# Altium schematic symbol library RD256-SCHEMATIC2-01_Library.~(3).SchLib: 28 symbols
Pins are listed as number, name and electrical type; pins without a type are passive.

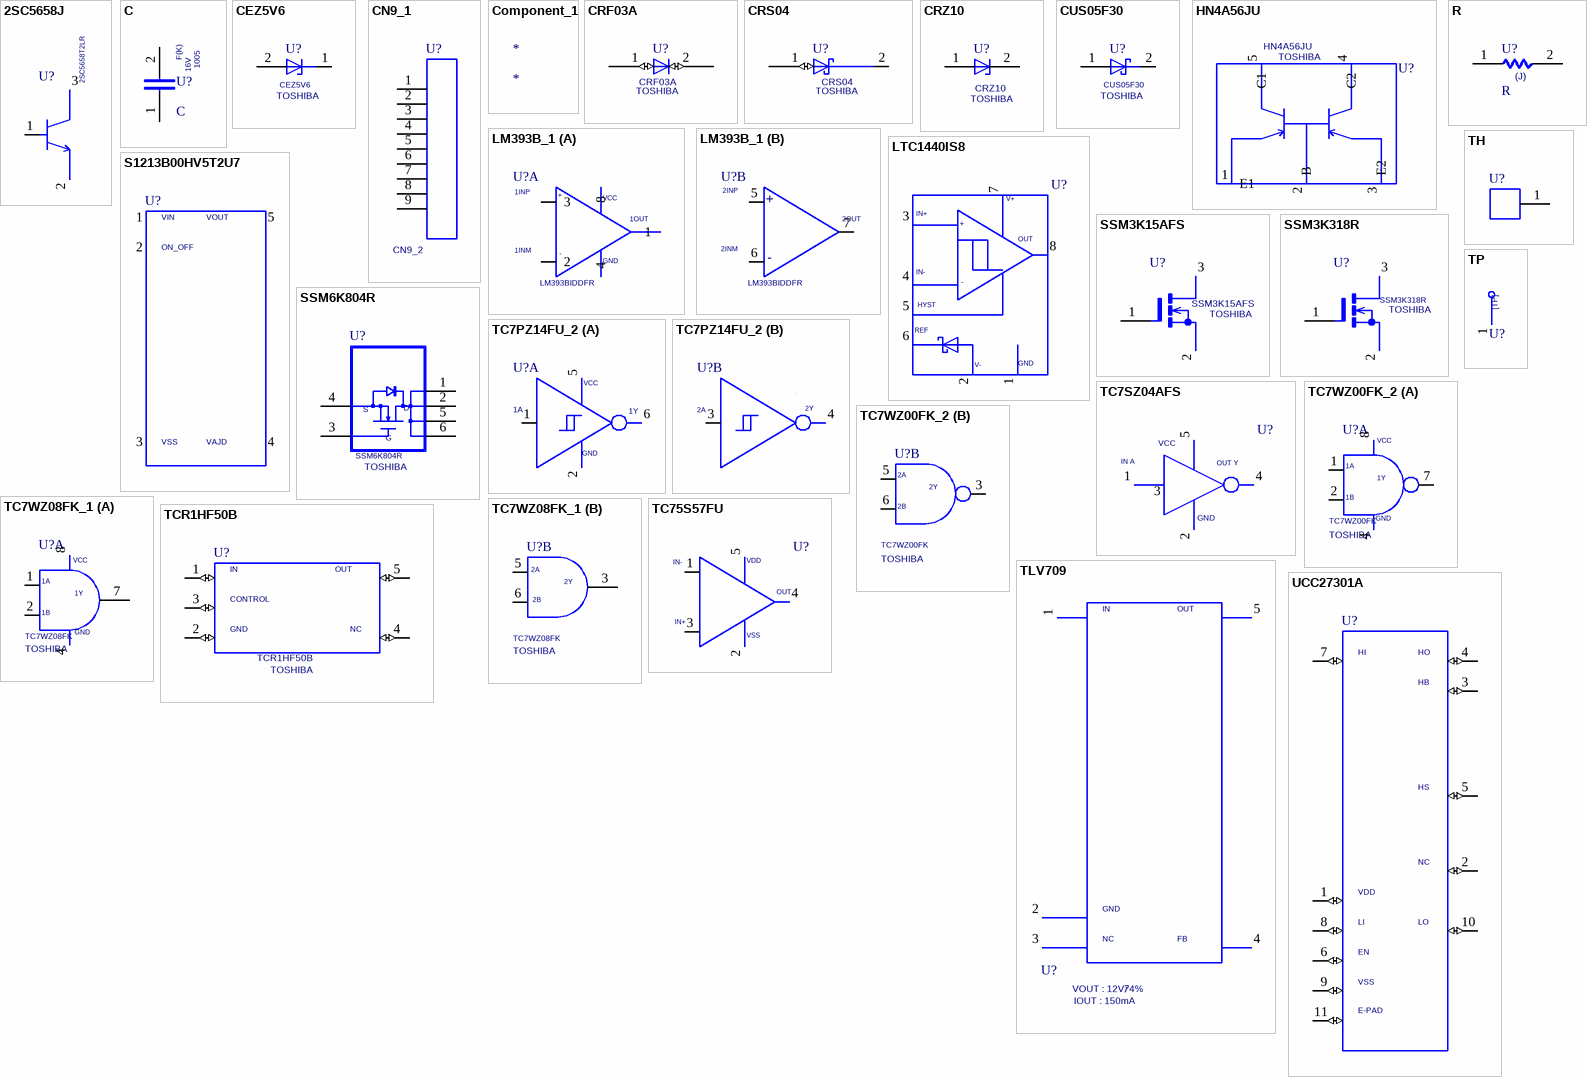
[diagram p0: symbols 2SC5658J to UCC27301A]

## 2SC5658J
designator U?  VAL1: 2SC5658T2LR  (hidden comment: 2SC5658J)
ORIGINALSYMBOLORIGIN: (0,0); PSPICETEMPLATE: X^@REFDES %C %B %E @MODEL; SAVEAREA0: -6194,-158,18648,15662; VENDOR: ROHM; SAVECOUNT: 8; UPDATETIME: 15:12:10; UPDATEUSER: 19910145; TIME: 09:39:04; Altium-Right: 20; Altium-Bottom: 80
simulation model 2SC5658J
pins: 1 B, 2 E, 3 C

## C
designator U?  VOLTAGE: 16VODE: 1005  VAL1: F(K)  (hidden comment: C)
ORIGINALSYMBOLORIGIN: (0,0); VC2: 0; PSPICETEMPLATE: C^@REFDES %1 %2 ?TOLERANCE¦C^@REFDES¦ @VALUE ?IC/IC=@IC/ TC=@TC1,@TC2 ?TOLERANCE¦\n.model C^@REFDES CAP C=1 DEV=@TOLERANCE% TC1=@TC1 TC2=@TC2 VC1=@VC1 VC2=@VC2¦; SAVECOUNT: 2; UPDATETIME: 08:48:12; UPDATEUSER: HP_Z8_KEYSHOT; Altium-Right: 20; Altium-Bottom: 10
simulation model C
pins: 1, 2

## CEZ5V6
designator U?  VENDOR: TOSHIBA  (hidden comment: CEZ5V6)
ORIGINALSYMBOLORIGIN: (0,0); PSPICETEMPLATE: X^@REFDES %C %A @MODEL; SAVEAREA0: -4630,-153,17114,13055; SAVECOUNT: 9; UPDATETIME: 08:16:22; UPDATEUSER: fukuda-y; TIME: 14:49:55; Altium-Right: 20
simulation model CEZ5V6
pins: 1 C, 2 A

## CN9_1
designator U?, comment CN9_2
OriginalSymbolOrigin: (0,0); USER_VALUE: XG4A-1031; COMP: CN9_1; PSPICETEMPLATE: X^@REFDES %1 %2 %3 %4 %5 %6 %7 %8 %9 %10 %M1 %M2 @MODEL; SAVECOUNT: 2; UPDATETIME: 08:48:13; UPDATEUSER: HP_Z8_KEYSHOT; Altium-Right: 20; Altium-Bottom: 120
simulation model CN9_1
pins: 1, 2, 3, 4, 5, 6, 7, 8, 9

## Component_1
designator *

## CRF03A
designator U?  VENDOR: TOSHIBA  (hidden comment: CRF03A)
OriginalSymbolOrigin: (0,0); PSPICETEMPLATE: X^@REFDES %A %C @MODEL; SAVECOUNT: 2; UPDATETIME: 08:48:14; UPDATEUSER: HP_Z8_KEYSHOT; Altium-Right: 10; Altium-Bottom: 20
simulation model CRF03A
pins: 1 A (io), 2 C (io)

## CRS04
designator U?  VENDOR: TOSHIBA  (hidden comment: CRS04)
OriginalSymbolOrigin: (0,0); PSPICETEMPLATE: X^@REFDES %A %C @MODEL; SAVECOUNT: 2; UPDATETIME: 08:48:14; UPDATEUSER: HP_Z8_KEYSHOT; Altium-Right: 40; Altium-Bottom: 20
simulation model CRS04
pins: 1 A (io), 2 C (io)

## CRZ10
designator U?  VENDOR: TOSHIBA  (hidden comment: CRZ10)
ORIGINALSYMBOLORIGIN: (0,0); PSPICETEMPLATE: X^@REFDES %A %C @MODEL; SAVEAREA0: -4630,-153,17114,13055; SAVECOUNT: 6; UPDATETIME: 08:18:42; UPDATEUSER: fukuda-y; TIME: 14:49:55; Altium-Right: 10; Altium-Bottom: 20
simulation model CRZ10
pins: 1 A, 2 C

## CUS05F30
designator U?  VENDOR: TOSHIBA  (hidden comment: CUS05F30)
ORIGINALSYMBOLORIGIN: (0,0); PSPICETEMPLATE: X^@REFDES %A %C @MODEL; SAVEAREA0: -4630,-153,17114,13055; SAVECOUNT: 9; UPDATETIME: 08:16:22; UPDATEUSER: fukuda-y; TIME: 14:49:55; Altium-Right: 20
simulation model CUS05F30
pins: 1 A, 2 C

## HN4A56JU
designator U?  VENDOR: TOSHIBA  (hidden comment: HN4A56JU)
OriginalSymbolOrigin: (0,0); PSPICETEMPLATE: X^@REFDES %B1 %E %B2 %C2 %C1 @MODEL; SAVECOUNT: 2; UPDATETIME: 08:48:13; UPDATEUSER: HP_Z8_KEYSHOT; Altium-Right: 120; Altium-Bottom: 80
simulation model HN4A56JU
pins: 1 E1 (io), 2 B (io), 3 E2 (io), 4 C2 (io), 5 C1 (io)

## LM393B_1
designator U?  VAL1: LM393BIDDFR  (hidden comment: LM393B_1)
OriginalSymbolOrigin: (2540,0); SWAP_INFO: (S1+S2); VENDOR: TI; COMP: LM393B_2; PSPICETEMPLATE: X^@REFDES %INN %VSS %INP %OUT %VDD @MODEL; SPLIT_INST: TRUE; SAVECOUNT: 5; UPDATETIME: 19:15:42; UPDATEUSER: t5459927; TIME: 08:48:12; Altium-Right: 70; Altium-Bottom: 60; Altium-Right1: 50
simulation model LM393B_1
part A pins: 1 (io), 2 (io), 3 (io), 4 (io), 8 (io)
part B pins: 5 (io), 6 (io), 7 (io)

## LTC1440IS8
designator U?  (value not drawn)
OriginalSymbolOrigin: (0,0); PSPICETEMPLATE: X^@REFDES %GND %V- %IN+ %IN- %HYST %REF %V+ %OUT @MODEL; SAVECOUNT: 4; UPDATETIME: 17:22:21; UPDATEUSER: t5459927; TIME: 08:48:16; Altium-Right: 90; Altium-Bottom: 120
simulation model LTC1440IS8
pins: 1 GND (io), 2 V- (io), 3 IN+ (io), 4 IN- (io), 5 HYST (io), 6 REF (io), 7 V+ (io), 8 OUT (io)

## R
designator U?  VAL1: (J)  (hidden comment: R)
ORIGINALSYMBOLORIGIN: (0,0); PSPICETEMPLATE: R^@REFDES %1 %2 ?TOLERANCE¦R^@REFDES¦ @VALUE TC=@TC1,@TC2 ?TOLERANCE¦\n.model R^@REFDES RES R=1 DEV=@TOLERANCE% TC1=@TC1 TC2=@TC2¦; TC2: 0; VAL2: 0.125; SAVECOUNT: 2; UPDATETIME: 08:48:13; UPDATEUSER: HP_Z8_KEYSHOT; Altium-Right: 20
simulation model R
pins: 1, 2

## S1213B00HV5T2U7
designator U?  (value not drawn)
OriginalSymbolOrigin: (0,0); PSPICETEMPLATE: X^@REFDES %ADJUST %OUTPUT %INPUT @MODEL; SAVECOUNT: 7; UPDATETIME: 09:48:38; UPDATEUSER: t5459927; TIME: 08:48:13; Altium-Right: 80; Altium-Bottom: 170
simulation model S1213B00HV5T2U7
pins: 1 (in), 2 (in), 3 (in), 4 (io), 5 (out)

## SSM3K15AFS
designator U?  VENDOR: TOSHIBA  (hidden comment: SSM3K15AFS)
PSPICETEMPLATE: X^@REFDES %D %G %S @MODEL; ORIGINALSYMBOLORIGIN: (0,0); SAVECOUNT: 2; UPDATETIME: 08:48:15; UPDATEUSER: HP_Z8_KEYSHOT; Altium-Right: 30; Altium-Bottom: 70
simulation model SSM3K15AFS
pins: 1 G, 2 S, 3 D

## SSM3K318R
designator U?  VENDOR: TOSHIBA  (hidden comment: SSM3K318R)
PSPICETEMPLATE: X^@REFDES %D %G %S @MODEL; ORIGINALSYMBOLORIGIN: (0,0); SAVECOUNT: 2; UPDATETIME: 08:48:16; UPDATEUSER: HP_Z8_KEYSHOT; Altium-Right: 30; Altium-Bottom: 70
simulation model SSM3K318R
pins: 1 G, 2 S, 3 D

## SSM6K804R
designator U?  VENDOR: TOSHIBA  (hidden comment: SSM6K804R)
PSPICETEMPLATE: X^@REFDES %1 %2 %3 %4 %5 %6 @MODEL; ORIGINALSYMBOLORIGIN: (0,0); SAVEAREA0: -7120,-295,29516,23636; SAVECOUNT: 14; UPDATETIME: 08:48:15; UPDATEUSER: HP_Z8_KEYSHOT; Altium-Right: 50; Altium-Bottom: 70
simulation model SSM6K804R
pins: 1, 2, 3, 4, 5, 6

## TC7PZ14FU_2
designator U?, comment TC7PZ17FU  (value not drawn)
OriginalSymbolOrigin: (5080,15240); SWAP_INFO: (S1+S2); VENDOR: TOSHIBA; COMP: TC7PZ17FU_2; PSPICETEMPLATE: X^@REFDES %1A %GND %2A %2Y %VCC %1Y @MODEL; SPLIT_INST: TRUE; SAVECOUNT: 7; UPDATETIME: 19:09:34; UPDATEUSER: t5459927; TIME: 11:55:01; Altium-Right: 70; Altium-Bottom: 60
simulation model TC7PZ14FU_2
part A pins: 1 (io), 2 (io), 5 (io), 6 (io)
part B pins: 3 (io), 4 (io)

## TC7SZ04AFS
designator U?  (value not drawn)
OriginalSymbolOrigin: (0,-5080); PSPICETEMPLATE: X^@REFDES %INA %GND %NC %OUTY %VCC @MODEL; VENDOR: TOSHIBA; SAVECOUNT: 6; UPDATETIME: 19:30:29; UPDATEUSER: t5459927; TIME: 11:55:02; Altium-Right: 80; Altium-Bottom: 60
simulation model TC7SZ04AFS
pins: 1 (io), 2 (io), 3 (io), 4 (io), 5 (io)

## TC7WZ00FK_2
designator U?, comment TC7WZ00FK  VENDOR: TOSHIBA
PART NUMBER: TC7W00FK; ORIGINALSYMBOLORIGIN: (2540,-2540); DESCRIPTION-A: NAND 2ch Logic; PSPICETEMPLATE: X^@REFDES %1A %1B %2Y %GND %2A %2B %1Y %VCC @MODEL; ・: 7 V; SPLIT_INST: TRUE; ORDER: $pOrder; COMP: TC7WZ00FK_2; SWAP_INFO: (S1+S2); SAVECOUNT: 9; UPDATETIME: 16:09:46; UPDATEUSER: sptcae09; TIME: 08:52:39; Altium-Right: 50; Altium-Bottom: 60; Altium-Bottom1: 40
simulation model TC7WZ00FK_2
part A pins: 1, 2, 4, 7, 8
part B pins: 3 2Y, 5 2A, 6 2B

## TC7WZ08FK_1
designator U?, comment TC7WZ08FK  VENDOR: TOSHIBA
PART NUMBER: TC7W00FK; ORIGINALSYMBOLORIGIN: (2540,-2540); DESCRIPTION-A: NAND 2ch Logic; PSPICETEMPLATE: X^@REFDES %1A %1B %2Y %GND %2A %2B %1Y %VCC @MODEL; ・: 7 V; SPLIT_INST: TRUE; ORDER: $pOrder; COMP: TC7WZ08FK_2; SWAP_INFO: (S1+S2); SAVECOUNT: 9; UPDATETIME: 16:09:46; UPDATEUSER: sptcae09; TIME: 08:52:39; Altium-Right: 40; Altium-Bottom: 60
simulation model TC7WZ08FK_1
part A pins: 1, 2, 4, 7, 8
part B pins: 3, 5, 6

## TC75S57FU
designator U?  (value not drawn)
OriginalSymbolOrigin: (2540,0); PSPICETEMPLATE: X^@REFDES %INN %VSS %INP %OUT %VDD @MODEL; VENDOR: TOSHIBA; SAVECOUNT: 3; UPDATETIME: 11:03:38; UPDATEUSER: t5459927; TIME: 08:48:15; Altium-Right: 60
simulation model TC75S57FU
pins: 1 (io), 2 (io), 3 (io), 4 (io), 5 (io)

## TCR1HF50B
designator U?  VENDOR: TOSHIBA
OriginalSymbolOrigin: (-2540,0); PSPICETEMPLATE: X^@REFDES %IN %GND %CONTROL %NC %OUT @MODEL; SAVECOUNT: 4; UPDATETIME: 10:27:35; UPDATEUSER: t5459927; TIME: 11:54:59; Altium-Right: 110; Altium-Bottom: 60
simulation model TCR1HF50B
pins: 1 (io), 2 (io), 3 (io), 4 (io), 5 (io)

## TH
designator U?  (value not drawn)
ORIGINALSYMBOLORIGIN: (0,0); PSPICETEMPLATE: X^@REFDES %1 @MODEL; SAVECOUNT: 1; UPDATETIME: 18:11:32; UPDATEUSER: w20165dm; Altium-Right: 20
simulation model TH
pins: 1

## TLV709
designator U?  CLASS: IOUT : 150mA  NC: VOUT : 12Vｱ4%  (hidden comment: TLV709)
OriginalSymbolOrigin: (0,0); VAL1: TLV709A01DBVR; PSPICETEMPLATE: X^@REFDES %IN %GND %NC %FB %OUT @MODEL; SAVECOUNT: 5; UPDATETIME: 10:01:49; UPDATEUSER: t5459927; TIME: 08:48:16; Altium-Right: 140; Altium-Bottom: 240
simulation model TLV709
pins: 1 (io), 2 (io), 3 (io), 4 (io), 5 (io)

## TP
designator U?  (value not drawn)
ORIGINALSYMBOLORIGIN: (0,0); SAVEAREA0: -242,-92,12810,7836; SAVECOUNT: 2; UPDATETIME: 16:18:11; UPDATEUSER: fukuda-y; TIME: 16:12:21; Altium-Right: 20; Altium-Bottom: 30
pins: 1

## UCC27301A
designator U?  (value not drawn)
OriginalSymbolOrigin: (5080,60960); PSPICETEMPLATE: X^@REFDES %VDD %NC %HB %HO %HS %EN %HI %LI %VSS %LO %THERMAL_PAD @MODEL; VAL1: UCC27301ADRCR; SAVECOUNT: 11; UPDATETIME: 20:55:41; UPDATEUSER: t5459927; TIME: 08:48:14; Altium-Right: 70; Altium-Bottom: 280
simulation model UCC27301A
pins: 1 (io), 2 (io), 3 (io), 4 (io), 5 (io), 6 (io), 7 (io), 8 (io), 9 (io), 10 (io), 11 (io)

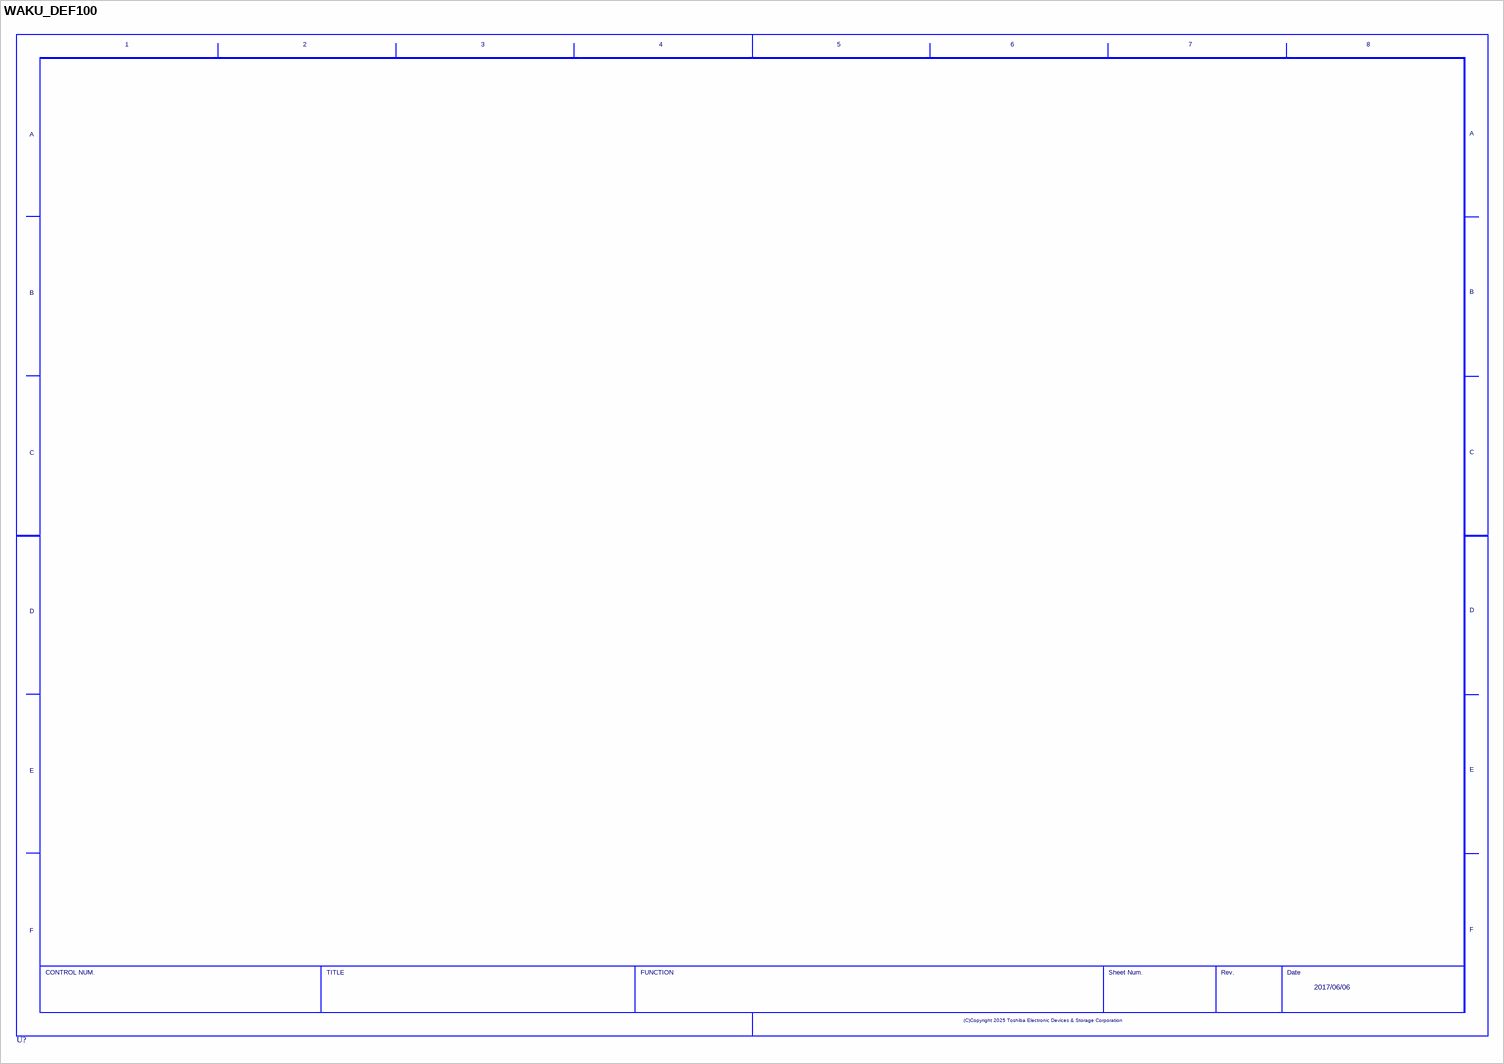
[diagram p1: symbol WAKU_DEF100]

## WAKU_DEF100
designator U?  DATE: 2017/06/06  (hidden comment: WAKU_DEF100)
OriginalSymbolOrigin: (10160,284480); SAVECOUNT: 4; UPDATETIME: 16:48:10; UPDATEUSER: t5459927; TIME: 14:30:25; SAVEAREA0: -63393,-16950,474261,314592; PLOTTIME: HH:MM; Altium-Right: 1570; Altium-Bottom: 1070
